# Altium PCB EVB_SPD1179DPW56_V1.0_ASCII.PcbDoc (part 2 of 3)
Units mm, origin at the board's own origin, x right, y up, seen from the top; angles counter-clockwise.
Board outline 135 x 90 mm, 4 copper layers (Top Layer, GND, L3, Bottom Layer), stack 0.603 mm thick; 336 components, 177 nets, 814 pads, 1056 vias.
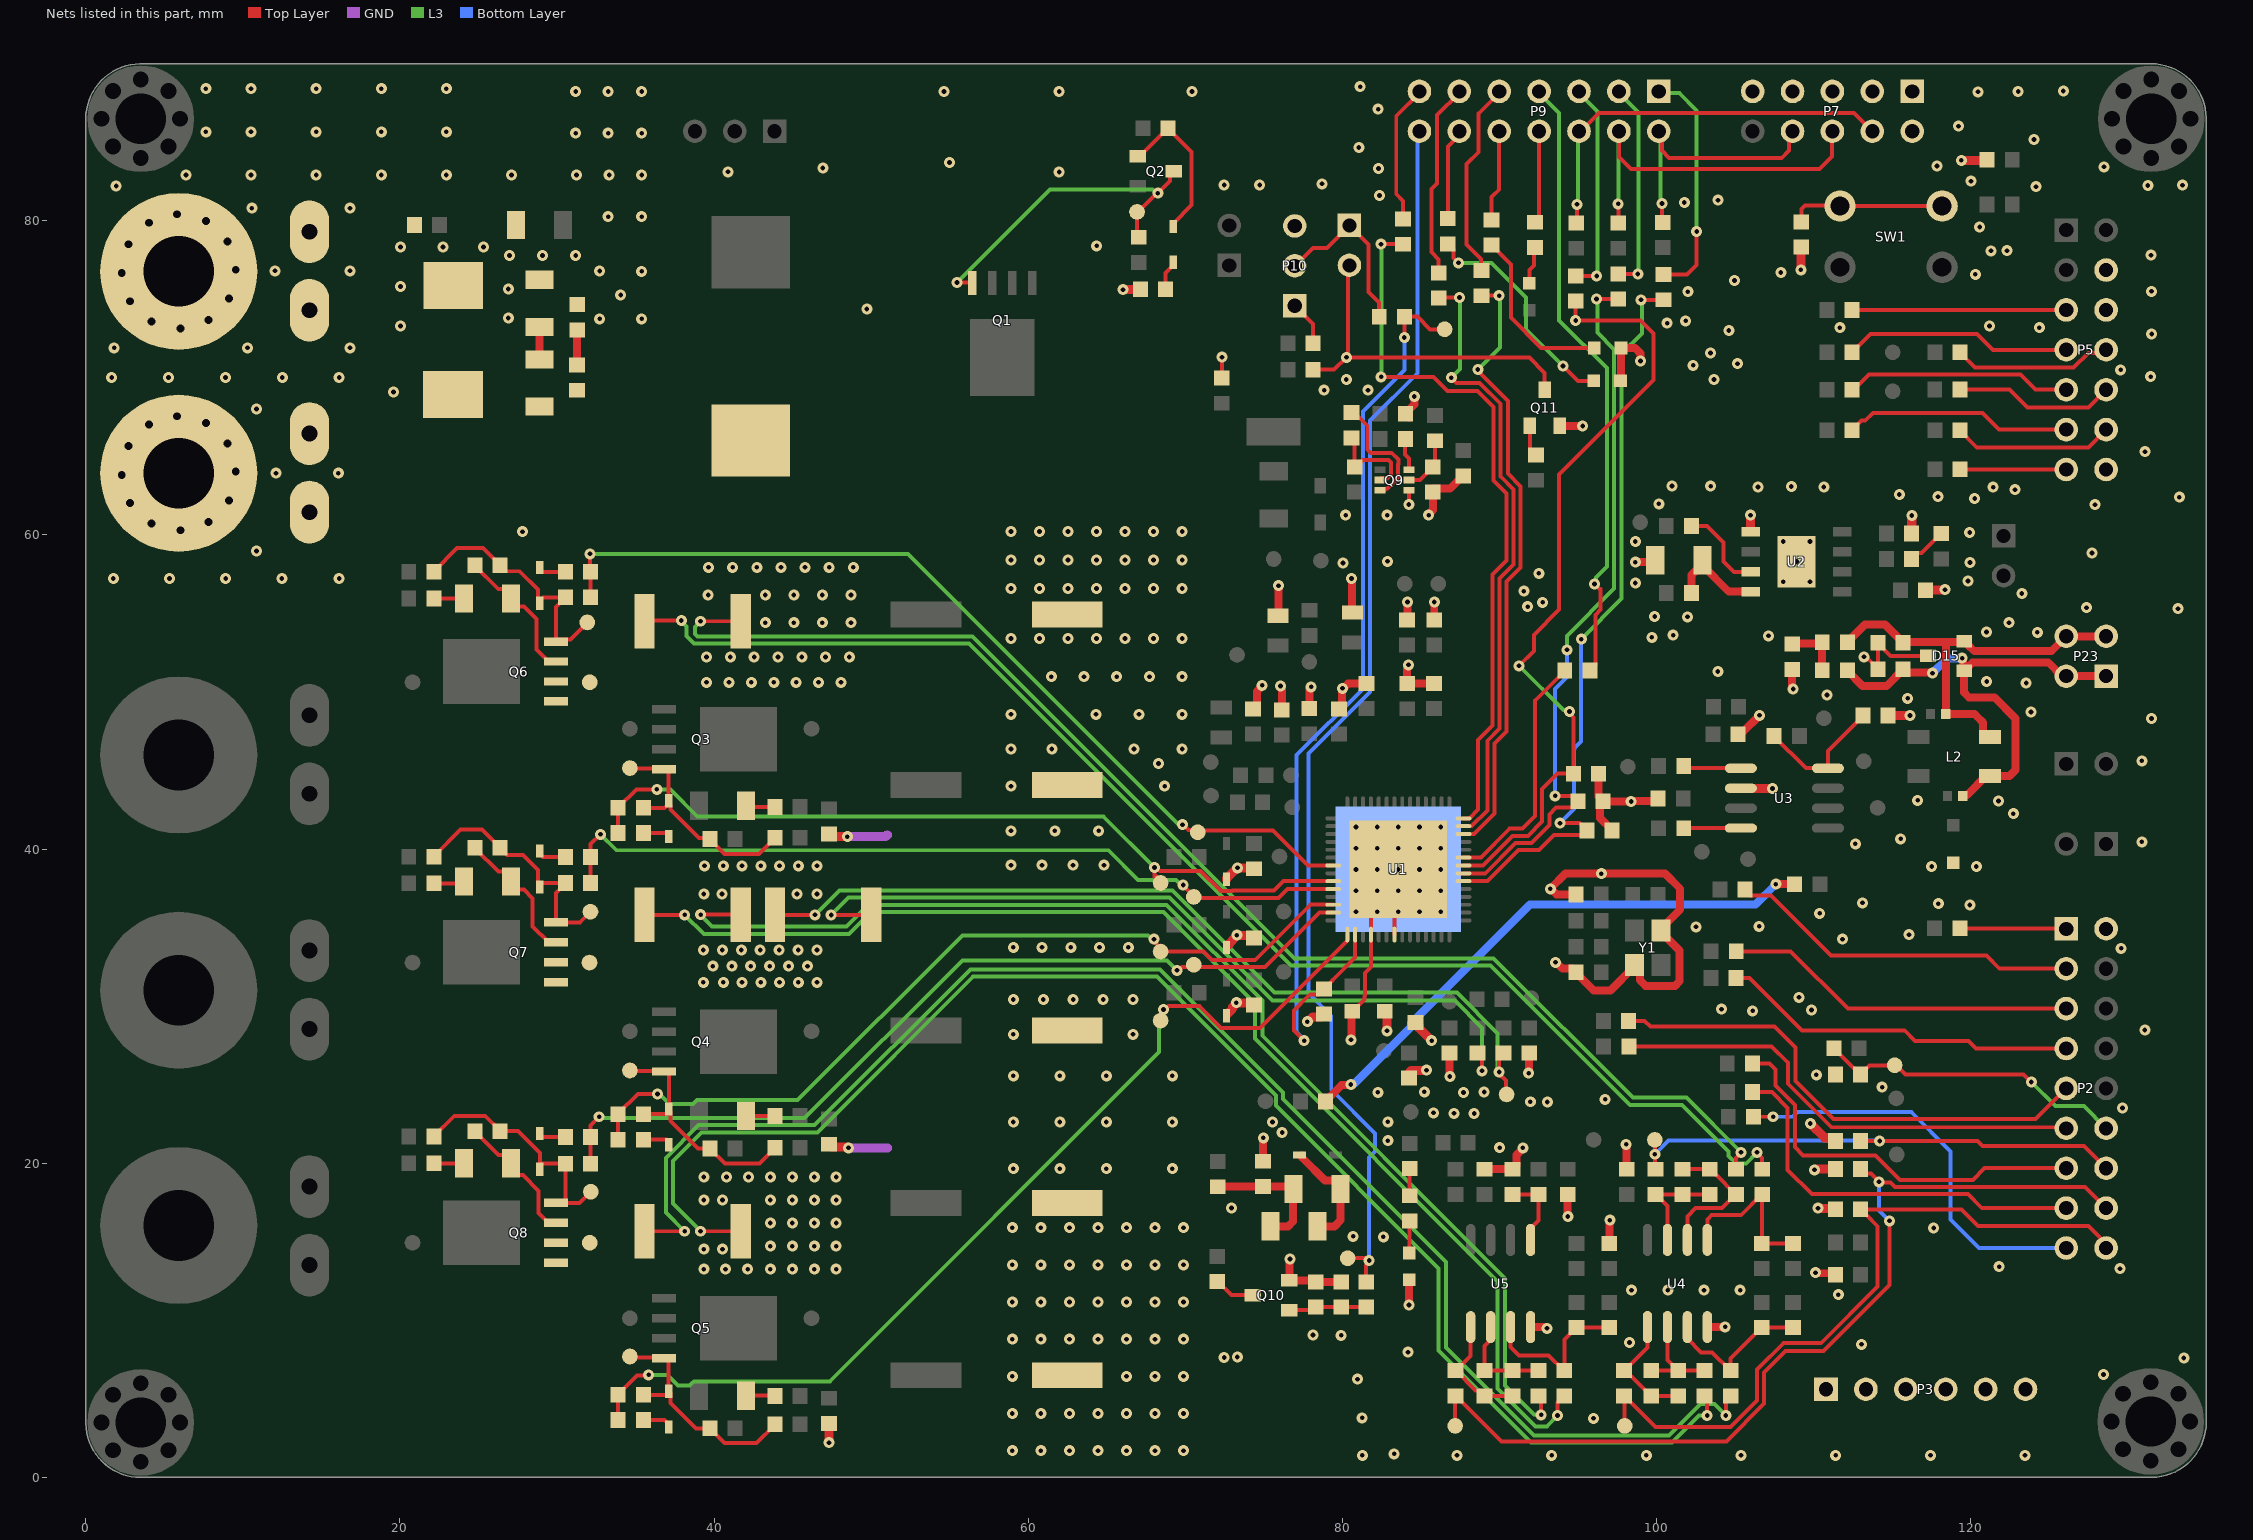
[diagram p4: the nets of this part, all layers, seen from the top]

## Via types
v1: diameter 0.7, hole 0.3, Top Layer to Bottom Layer, tented both sides, 810 vias
v2: diameter 0.5, hole 0.2, Top Layer to Bottom Layer, tented both sides, 161 vias
v3: diameter 0.9, hole 0.5, Top Layer to Bottom Layer, 60 vias
v4: diameter 0.6, hole 0.3, Top Layer to Bottom Layer, tented top, 25 vias

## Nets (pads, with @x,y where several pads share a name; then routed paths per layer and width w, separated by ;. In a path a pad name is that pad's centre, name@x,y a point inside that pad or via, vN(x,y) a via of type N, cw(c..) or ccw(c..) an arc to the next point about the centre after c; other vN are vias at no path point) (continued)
GND: C1.2 C2.1 C5.2 C6.2 C7.1 C8.1 C10.2 C11.1 C12.1 C13.1 C14.2 C15.2 C16.1 C17.1 C18.1 C19.1 C23.1 C24.1 C29.1 C30.1 C31.1 C32.1 C33.1 C34.1 C35.1 C36.1 C37.1 C38.1 C39.1 C40.1 C41.1 C44.1 C52.1 C53.1 C54.1 C55.1 C57.1 C58.1 C61.1 C62.1 C63.1 C64.1 C70.1 C71.1 C72.1 C73.1 C74.1 C77.1 C78.1 C80.1 C81.1 C83.1 C84.1 C85.2 C86.1 C87.2 C90.1 D1.1 D3.2 D4.2 D5.2 D13.2 D14.2 D15.3 D17.2 D18.1 P2.2 P3.1 P3.2 P3.3 P3.4 P3.5 P3.6 P5.4 P5.6 P5.14 P6.1 P7.1 P7.2 P7.3 P7.5 P7.7 P7.9 P10.3 pad.1@5.918,76.784 Q9.1 Q10.2 Q11.2 R7.1 R9.2 R11.1 R55.1 R57.1 R58.1 R85.2 R86.1 R94.1 R98.2 R99.1 R109.2 U1.46 U1.49 U1.57 U2.5 U2.9 U3.2 U4.4 U5.4 Y1.2 Y1.4 | length 203
  Top Layer w0.254: v1(47.459,35.808) 50,35.808 R55.1@50.005,35.814 ; R109.2@72.314,69.99 72.339,70.015 v1(72.339,71.323) ; C78.1@80.629,29.68 80.654,29.68 81.402,30.428 81.402,30.615 81.456,30.67 81.456,31.89 81.439,31.907 81.439,32.117 81.816,32.494 U1.46@81.816,34.187 ; U1.46@81.816,34.56 81.816,36.96 v4(82.216,37.359) U1.57@83.316,38.46 ; C7.1@82.703,29.68 C7.1@82.85,29.533 ; U1.49@83.316,34.56 U1.57@83.316,38.46 ; v4(83.566,38.71) U1.57@83.316,38.46 ; v1(84.232,61.945) Q9.1@84.232,62.85 ; R58.1@88.605,27.021 88.901,26.725 88.898,26.722 v1(88.898,25.889) ; U3.2@105.371,43.877 U3.2@105.382,43.866 ; U2.5@105.98,60.225 U2.5@106.007,60.198 ; v1@107.38,43.866 v1(107.391,43.855) ; R9.2@109.193,78.302 R9.2@109.22,78.329 ; v1(113.208,52.248) 113.293,52.162 113.42,52.162 C62.1@114.097,51.485 ; C62.1@114.097,51.46 C62.1@114.097,51.485 ; C54.1@114.097,53.137 C54.1@114.097,53.112 ; R86.1@114.749,48.514 R86.1@114.841,48.423 ; D15.3@117.29,52.299 114.91,52.299 C54.1@114.097,53.112 ; R11.1@121.004,83.849 R11.1@121.052,83.897 ; C62.1@114.097,51.485 C54.1@114.097,53.112
  Top Layer w0.508: C39.1@74.312,48.934 74.337,48.934 74.558,49.155 74.558,50.046 74.893,50.381 v1(74.893,50.433) ; C77.1@74.955,20.129 74.964,20.138 74.964,21.611 v1(74.973,21.62) ; C38.1@75.908,54.861 75.924,54.877 75.924,56.761 v1(75.94,56.777) ; v1(76.062,50.386) 76.062,50.334 76.144,50.253 C37.1@76.144,48.868 ; v1(76.667,13.9) 76.639,13.872 76.639,12.579 Q10.2@76.611,12.551 78.199,12.551 C80.1@78.313,12.437 R94.1@79.939,12.437 ; C36.1@77.9,48.947 77.9,50.17 78.012,50.283 v1(78.012,50.335) ; C33.1@79.785,48.922 79.977,49.114 79.977,50.204 v1(80.014,50.241) 80.066,50.241 80.375,50.55 C84.1@81.538,50.55 ; v1(80.557,27.861) 80.593,27.897 80.593,29.644 C78.1@80.629,29.68 ; v1@80.582,57.174 v1(80.582,57.226) 80.612,57.197 80.612,55.09 C35.1@80.642,55.06 ; C31.1@84.122,54.584 84.136,54.599 84.136,55.713 v1(84.15,55.728) ; v1@84.195,61.982 v1(84.232,61.945) ; v1(84.209,51.73) 84.209,51.678 84.128,51.597 C32.1@84.128,50.537 84.13,50.54 85.83,50.54 C30.1@85.833,50.542 ; R98.2@84.231,67.47 84.01,67.691 R98.2@84.01,67.716 84.01,67.741 84.585,68.316 v1(84.585,68.815) ; v1(84.244,10.977) 84.252,10.986 84.252,12.577 D17.2@84.261,12.586 ; v1(85.496,61.265) 85.496,61.317 85.765,61.586 R99.1@85.765,62.728 ; R99.1@85.83,62.949 86.857,62.949 87.676,63.768 C83.1@87.701,63.768 ; C29.1@85.852,54.584 v1(85.852,55.728) ; C53.1@86.827,27.021 86.835,27.013 86.835,25.53 v1(86.842,25.523) ; C70.1@89.057,19.621 R85.2@90.84,19.621 90.865,19.621 91.086,19.842 91.086,20.523 91.491,20.928 v1(91.491,20.98) ; v1(91.861,25.734) 91.884,25.757 91.884,26.998 C52.1@91.907,27.021 ; U5.4@91.983,9.572 92.898,9.572 92.983,9.487 v1(93.035,9.487) ; v1(93.565,32.79) 93.617,32.79 94.005,32.402 94.661,32.402 94.882,32.181 C12.1@94.882,32.156 ; Q11.2@93.835,66.947 95.284,66.947 v1(95.298,66.933) ; C72.1@94.345,18.021 94.349,18.017 94.349,16.62 v1(94.353,16.616) ; C12.1@94.882,32.131 96.007,31.006 97.066,31.006 98.591,32.531 Y1.4@98.591,32.631 98.937,32.285 98.937,31.67 99.314,31.293 101.175,31.293 101.473,31.59 101.473,33.549 100.291,34.731 Y1.2@100.291,34.831 100.291,34.931 101.51,36.15 101.51,37.474 100.543,38.441 94.21,38.441 v1(93.241,37.472) 93.282,37.472 93.645,37.109 C13.1@94.882,37.109 ; C87.2@96.321,44.803 96.321,43.354 96.608,43.067 C86.1@96.608,43.042 ; C74.1@96.987,14.897 97.007,14.917 97.007,16.354 v1(97.027,16.374) ; C85.2@97.181,41.18 97.181,41.205 96.406,41.98 96.406,42.84 C86.1@96.608,43.042 ; D13.2@97.711,69.809 97.727,69.825 97.727,71.889 D14.2@97.743,71.905 98.646,71.905 98.987,71.564 v1(98.987,71.077) ; v1(98.075,21.208) 98.09,21.192 98.09,19.637 C71.1@98.106,19.621 ; v1(98.654,58.268) 99.795,58.268 C55.1@99.922,58.395 ; C58.1@100.104,43.197 99.98,43.073 98.423,43.073 v1(98.386,43.036) 98.383,43.039 96.611,43.039 C86.1@96.608,43.042 ; U4.4@103.237,9.572 103.244,9.579 104.365,9.579 v1(104.372,9.586) ; C61.1@105.015,47.141 C61.1@105.194,47.32 C61.1@105.194,47.345 ; C61.1@105.531,47.492 106.521,48.483 v1(106.558,48.52) ; C57.1@108.636,51.448 108.636,50.315 108.704,50.247 v1(108.704,50.195) ; v1(110.126,13.035) 110.163,12.998 111.297,12.998 C73.1@111.392,12.903
  Top Layer w0.58: v1(47.32,2.21) C18.1@47.32,3.442 ; C16.1@47.32,21.212 47.505,21.027 48.485,21.027 48.532,20.98 v1(48.565,20.98) ; C17.1@47.32,40.964 47.469,40.815 48.466,40.815 v1(48.489,40.792) ; v1(66.04,75.616) 66.053,75.629 67.132,75.629 R7.1@67.145,75.641 ; D5.2@72.628,38.078 72.628,38.148 73.269,38.788 73.307,38.788 v1(73.33,38.811) 73.353,38.788 74.343,38.788 C24.1@74.381,38.751 ; D3.2@72.688,29.521 73.011,29.843 73.011,29.951 73.254,30.194 v1(73.254,30.226) 73.277,30.203 74.242,30.203 C19.1@74.381,30.064 ; D4.2@72.688,33.864 73.011,34.187 73.011,34.218 73.279,34.486 v1(73.279,34.519) 73.302,34.496 74.239,34.496 C23.1@74.381,34.354 ; v1(77.773,29.011) 77.805,29.011 78.116,29.321 78.644,29.321 C8.1@78.829,29.506 ; v1(82.85,28.429) C7.1@82.85,29.533 ; C40.1@84.271,25.785 84.388,25.901 85.331,25.901 v1(85.354,25.924) ; C41.1@84.653,28.953 84.678,28.953 84.863,28.768 84.863,28.625 v1(85.686,27.802) ; C58.1@100.104,43.197 C58.1@100.104,43.222 ; U3.2@105.382,43.866 v1@107.38,43.866 ; U2.5@105.98,60.225 v1(105.98,61.257) ; v1(109.193,76.879) R9.2@109.193,78.302 ; v1(109.796,22.534) 110.708,21.622 111.207,21.622 111.392,21.437 C63.1@111.392,21.412 ; v1(110.058,19.583) 110.091,19.583 110.141,19.634 C81.1@111.392,19.634 ; v1(110.287,17.145) 110.31,17.122 111.339,17.122 C64.1@111.392,17.069 ; R86.1@114.749,48.514 v1(116.138,48.514) ; R57.1@116.243,60.096 116.249,60.103 116.249,61.233 v1(116.256,61.239) ; C44.1@117.132,56.49 117.145,56.502 118.351,56.502 v1(118.364,56.515) ; v1(119.41,83.849) R11.1@121.004,83.849
  GND w0.58: v1(48.489,40.792) 50.927,40.792 51.029,40.894 ; v1(48.565,20.98) 51.054,20.98
  L3 w0.254: v1(47.459,35.808) 48.557,36.906 69.003,36.906 75.556,30.353 87.161,30.353 88.898,28.616 v1(88.898,25.889)
  other v1: 81.272,1.401 87.3,1.401 93.328,1.401 99.357,1.401 105.385,1.401 111.413,1.401 117.441,1.401 123.469,1.401 83.297,1.505 58.991,1.702 60.808,1.702 62.624,1.702 64.44,1.702 66.256,1.702 68.072,1.702 69.888,1.702 95.987,3.759 81.259,3.79 58.991,4.068 60.808,4.068 62.624,4.068 64.44,4.068 66.256,4.068 68.072,4.068 69.888,4.068 80.966,6.256 58.991,6.435 66.256,6.435 68.072,6.435 69.888,6.435 128.465,6.558 133.571,7.599 72.48,7.631 73.317,7.663 84.177,7.97 113.053,8.476 98.289,8.592 58.991,8.801 60.808,8.801 62.624,8.801 64.44,8.801 66.256,8.801 68.072,8.801 69.888,8.801 79.931,9.044 78.134,9.066 58.991,11.168 60.808,11.168 62.624,11.168 64.44,11.168 66.256,11.168 68.072,11.168 69.888,11.168 111.574,11.638 98.416,11.919 100.719,11.919 103.022,11.919 105.325,11.919 129.507,13.289 121.819,13.415 58.991,13.534 60.808,13.534 62.624,13.534 64.44,13.534 66.256,13.534 68.072,13.534 69.888,13.534 82.61,15.316 80.694,15.351 117.645,15.879 58.991,15.9 60.808,15.9 62.624,15.9 64.44,15.9 66.256,15.9 68.072,15.9 69.888,15.9 72.94,17.151 59.055,19.66 62.014,19.66 64.973,19.66 69.173,19.66 90.013,20.989 82.897,21.435 76.173,21.965 59.055,22.624 62.014,22.631 64.973,22.624 69.173,22.624 75.554,22.621 82.898,22.636 88.392,23.162 87.106,23.181 85.81,23.21 129.667,23.52 93.048,23.899 91.968,23.917 96.73,24.068 82.262,24.513 87.709,24.501 85.217,24.549 89.028,24.534 114.368,24.846 59.055,25.571 62.014,25.571 64.973,25.571 69.173,25.571 110.177,25.633 59.055,28.212 66.675,28.212 131.09,28.481 106.128,29.705 109.873,29.764 104.139,29.81 59.055,30.429 60.96,30.429 62.865,30.429 64.77,30.429 66.675,30.429 109.075,30.561 129.583,33.685 59.055,33.749 60.884,33.749 62.713,33.749 64.541,33.749 66.37,33.749 111.848,34.268 116.078,34.556 102.519,35.052 106.542,35.086 110.391,35.915 119.946,36.445 117.946,36.53 113.124,36.58 96.484,38.438 117.518,38.892 120.363,38.892 58.903,38.982 60.878,38.982 62.854,38.982 64.83,38.982 112.664,40.334 130.902,40.462 115.547,40.655 58.903,41.166 61.697,41.166 64.491,41.166 122.719,42.258 121.772,43.059 116.633,43.112 58.903,44.011 68.691,44.011 68.3,45.452 130.902,45.618 58.903,46.373 61.503,46.373 66.735,46.373 69.799,46.373 131.512,48.315 58.903,48.583 64.313,48.583 67.056,48.583 69.799,48.583 123.842,48.732 115.997,49.603 110.861,49.814 123.541,50.577 121.023,50.677 61.468,50.978 63.551,50.978 65.634,50.978 67.716,50.978 69.799,50.978 103.91,51.313 58.903,53.416 60.719,53.416 62.535,53.416 64.351,53.416 66.167,53.416 67.983,53.416 69.799,53.416 99.7,53.483 107.133,53.582 101.064,53.619 124.249,53.802 121.006,53.823 122.447,54.416 101.973,54.792 99.883,54.805 133.209,55.306 127.373,55.376 91.796,55.439 92.754,55.712 123.257,56.28 91.556,56.423 58.903,56.591 60.719,56.591 62.535,56.591 64.351,56.591 66.167,56.591 67.983,56.591 69.799,56.591 98.654,56.947 108.066,57.026 109.768,57.026 119.833,57.077 92.506,57.56 80.041,58.22 119.956,58.243 82.872,58.323 108.917,58.309 58.903,58.407 60.719,58.407 62.535,58.407 64.351,58.407 66.167,58.407 67.983,58.407 69.799,58.407 127.726,58.847 98.654,59.588 108.066,59.592 109.768,59.592 119.943,60.163 58.903,60.223 60.719,60.223 62.535,60.223 64.351,60.223 66.167,60.223 67.983,60.223 69.799,60.223 80.213,61.265 82.855,61.265 127.923,61.933 100.146,61.982 120.258,62.33 133.284,62.408 117.918,62.436 115.457,62.585 122.825,62.884 121.438,63.043 106.467,63.061 110.658,63.061 108.584,63.089 100.989,63.12 103.447,63.107 131.107,65.302 78.842,69.219 81.628,69.219 80.251,69.895 103.659,69.906 131.466,70.078 129.557,70.515 102.334,70.804 105.164,70.91 103.436,71.591 1.809,71.914 10.293,71.914 16.821,71.914 131.524,72.795 104.607,73.013 111.671,73.197 124.37,73.197 20.041,73.304 121.201,73.309 100.683,73.488 101.863,73.631 32.715,73.762 35.393,73.762 26.899,73.812 49.725,74.392 34.054,75.286 101.998,75.495 131.515,75.51 26.899,75.667 20.041,75.819 104.972,76.209 120.298,76.595 107.914,76.707 35.393,76.784 12.045,76.816 16.821,76.816 32.715,76.81 26.975,77.8 29.083,77.8 31.191,77.8 131.481,77.818 121.293,78.096 122.314,78.103 20.041,78.334 22.746,78.334 25.324,78.334 64.364,78.413 120.579,79.612 33.259,80.262 35.393,80.262 10.572,80.804 16.821,80.804 101.773,81.17 103.911,81.314 82.368,81.614 124.165,82.178 1.93,82.22 131.281,82.25 74.742,82.278 133.494,82.275 72.48,82.288 78.703,82.356 120.028,82.527 6.378,82.92 10.523,82.92 14.668,82.92 18.813,82.92 22.958,82.92 27.103,82.92 31.248,82.92 33.32,82.92 35.393,82.92 40.891,83.121 61.976,83.112 82.307,83.332 46.928,83.367 128.491,83.443 117.866,83.487 54.989,83.715 81.053,84.673 124.03,85.186 31.191,85.579 33.259,85.579 35.393,85.579 7.645,85.669 10.523,85.669 14.668,85.669 18.813,85.669 22.958,85.669 119.231,86.025 82.282,87.106 120.473,88.212 31.191,88.237 33.259,88.237 35.393,88.24 54.635,88.24 61.976,88.24 70.434,88.24 123.028,88.23 125.898,88.265 7.645,88.417 10.523,88.417 14.668,88.417 18.813,88.417 22.958,88.417 81.138,88.543
  other v3: 6.02,73.152 4.19,73.588 7.822,73.689 2.823,74.88 9.115,75.056 2.286,76.683 9.55,76.886 2.722,78.512 9.013,78.688 4.014,79.879 7.646,79.981 5.817,80.416
  other v4: 80.865,36.009 82.216,36.009 83.566,36.009 84.916,36.009 86.267,36.009 80.865,37.359 83.566,37.359 84.916,37.359 86.267,37.359 80.865,38.71 82.216,38.71 84.916,38.71 86.267,38.71 80.865,40.06 82.216,40.06 83.566,40.06 84.916,40.06 86.267,40.06 80.865,41.411 82.216,41.411 83.566,41.411 84.916,41.411 86.267,41.411
HALL_A: P7.8 P9.2 R117.1 | length 16.7
  Top Layer w0.254: P9.2@100.339,85.414 100.339,84.466 100.81,83.995 107.975,83.995 108.444,84.465 P7.8@108.444,85.414 ; v1(100.355,81.106) 100.355,79.942 R117.1@100.397,79.899
  Top Layer w0.508: P9.2@100.149,85.604 P9.2@100.339,85.414 ; P7.8@108.444,85.414 P7.8@108.634,85.604
  L3 w0.254: P9.2@100.149,85.604 100.27,85.484 100.27,81.191 v1(100.355,81.106)
HALL_B: P7.6 P9.4 R118.1 | length 23
  Top Layer w0.254: R118.1@97.57,79.858 v1@97.57,80.881 ; P9.4@97.609,85.604 97.609,84.078 98.388,83.299 110.386,83.299 111.174,84.087 111.174,85.675 P7.6@111.202,85.704
  Top Layer w0.508: P9.4@97.59,85.585 P9.4@97.609,85.604
  L3 w0.254: v1@97.583,81.111 P9.4@97.583,85.578
  L3 w0.508: v1(97.558,81.085) v1@97.583,81.111 ; P9.4@97.583,85.578 P9.4@97.609,85.604
HALL_C: P7.4 P9.6 R119.1 | length 25.6
  Top Layer w0.254: v1(94.94,81.055) 94.94,79.943 R119.1@94.958,79.925 ; P9.6@95.069,85.604 96.327,86.862 112.584,86.862 P7.4@113.742,85.704
  Top Layer w0.508: R119.1@94.889,79.856 R119.1@94.958,79.925 ; P9.6@94.979,85.514 P9.6@95.069,85.604
  L3 w0.254: v1(94.94,81.055) 95.005,81.12 95.005,85.54 P9.6@95.069,85.604
HO_U: R24.2 R27.2 TP11.1 U1.43 | length 63.7
  Top Layer w0.254: R24.2@33.896,3.658 R27.2@33.896,5.258 33.896,5.283 35.108,6.495 35.806,6.495 v1(35.839,6.528) ; TP11.1@68.428,29.083 TP11.1@68.428,29.285 ; v1(68.616,29.79) 68.737,29.79 68.944,29.997 70.901,29.997 72.272,28.626 74.753,28.626 80.316,34.189 U1.43@80.316,34.56
  L3 w0.254: v1(35.839,6.528) 37.022,6.528 37.712,5.837 38.425,5.837 38.71,6.121 47.371,6.121 68.342,27.093 68.342,29.418 68.616,29.692 v1(68.616,29.79)
HO_V: R23.2 R26.2 TP21.1 U1.40 | length 54.7
  Top Layer w0.254: R23.2@33.896,21.504 33.896,23.155 35.151,24.409 v1(36.398,24.409) ; v1(68.005,34.266) 68.091,34.18 68.091,34.016 68.428,33.679 TP21.1@68.428,33.477 71.172,33.477 71.697,32.952 74.456,32.952 77.963,36.46 U1.40@79.416,36.46
  L3 w0.254: v1(36.398,24.409) 36.519,24.409 37.154,23.774 38.659,23.774 38.913,24.028 45.325,24.028 55.807,34.51 67.64,34.51 67.885,34.266 v1(68.005,34.266)
HO_W: R22.2 R25.2 TP36.1 U1.37 | length 52.2
  Top Layer w0.254: R22.2@33.896,41.028 33.896,42.653 35.049,43.805 v1(36.357,43.805) ; TP36.1@68.428,37.846 TP36.1@68.285,37.989 ; U1.37@79.416,37.96 76.245,37.96 75.638,37.353 73.016,37.353 72.993,37.331 72.254,37.331 72.232,37.353 70.977,38.608 68.396,38.608 68.167,38.837 v1(68.047,38.837) 68.047,38.398 ; 68.047,38.398 68.047,38.227 TP36.1@68.285,37.989 ; 68.047,38.398 68.285,38.159 TP36.1@68.285,37.989
  L3 w0.254: v1(36.357,43.805) 36.378,43.785 37.215,43.785 38.937,42.062 64.805,42.062 68.03,38.837 v1(68.047,38.837)
IBS+: R51.1 R52.1 R53.1 R54.1 R55.2 R70.2 R71.2 R89.2 TP28.1 | length 314
  Top Layer w0.254: v1(39.141,15.672) R53.1@41.7,15.672 ; v1(39.141,54.508) R51.1@41.7,54.508 ; v1(39.15,35.823) 41.691,35.823 R52.1@41.7,35.814 ; R55.2@43.873,35.814 v1(46.431,35.814) ; R54.1@90.256,27.021 89.984,26.749 v1(89.984,25.808) 89.984,25.688 90.408,25.264 90.408,24.429 TP28.1@90.454,24.383 TP28.1@90.391,24.383 ; R89.2@92.491,5.194 92.659,5.026 v1(92.659,3.982) ; R71.2@103.057,5.194 103.226,5.026 v1(103.226,3.937) ; R70.2@105.057,19.621 105.057,20.346 105.385,20.674 v1(105.385,20.701)
  L3 w0.254: v1(39.141,15.672) 39.141,15.69 37.389,17.442 37.389,20.156 39.204,21.971 46.595,21.971 56.501,31.877 68.195,31.877 75.77,24.302 75.77,23.667 86.131,13.306 86.131,8.091 92.009,2.213 100.994,2.213 102.709,3.928 103.217,3.928 v1(103.226,3.937) ; v1(39.141,54.508) 39.141,54.492 38.786,54.137 38.786,53.692 38.935,53.543 56.464,53.543 76.962,33.045 89.637,33.045 98.501,24.181 101.905,24.181 v1(105.385,20.701) ; v1(39.15,35.823) 39.15,35.805 39.878,35.077 48.426,35.077 49.798,36.449 68.813,36.449 74.903,30.359 74.903,28.119 90.348,12.675 90.348,5.842 92.193,3.997 92.645,3.997 v1(92.659,3.982) ; v1(46.431,35.814) 47.981,37.363 69.192,37.363 75.694,30.861 87.3,30.861 89.891,28.27 v1@89.891,25.89
  other v1: 39.345,13.259 40.729,13.259 42.139,13.259 43.586,13.259 44.983,13.259 46.38,13.259 47.777,13.259 39.345,14.529 40.538,14.529 43.586,14.726 44.983,14.726 46.38,14.726 47.777,14.726 43.586,16.192 44.983,16.192 46.38,16.192 47.777,16.192 39.345,17.659 40.538,17.659 43.586,17.659 44.983,17.659 46.38,17.659 47.777,17.659 39.345,19.126 40.792,19.126 42.189,19.126 43.586,19.126 44.983,19.126 46.38,19.126 47.777,19.126 39.319,31.521 40.589,31.521 41.783,31.521 42.977,31.521 44.171,31.521 45.364,31.521 46.558,31.521 39.922,32.55 41.129,32.55 42.335,32.55 43.542,32.55 44.748,32.55 45.955,32.55 39.319,33.579 40.526,33.579 41.732,33.579 42.939,33.579 44.145,33.579 45.352,33.579 46.558,33.579 39.345,37.141 40.509,37.141 45.284,37.141 46.558,37.141 39.395,38.938 40.589,38.938 41.783,38.938 42.977,38.938 44.171,38.938 45.364,38.938 46.558,38.938 39.522,50.622 40.949,50.622 42.376,50.622 43.802,50.622 45.229,50.622 46.656,50.622 48.082,50.622 39.522,52.229 41.038,52.229 42.553,52.229 44.069,52.229 45.585,52.229 47.1,52.229 48.616,52.229 43.26,54.413 45.077,54.413 46.895,54.413 48.713,54.413 39.624,56.185 43.26,56.185 45.077,56.185 46.895,56.185 48.713,56.185 39.645,57.944 41.182,57.944 42.718,57.944 44.255,57.944 45.792,57.944 47.328,57.944 48.865,57.944
IDC: C90.2 P2.12 R122.1 TP47.1 | length 19.8
  Top Layer w0.254: R122.1@111.29,27.33 111.29,27.305 112.569,26.027 112.644,26.027 C90.2@112.992,25.679 ; C90.2@112.992,25.654 C90.2@112.992,25.679 ; TP47.1@115.164,26.238 113.576,26.238 113.365,26.027 113.34,26.027 C90.2@112.992,25.679 ; TP47.1@115.292,26.213 115.851,25.654 123.378,25.654 v1(123.861,25.171)
  L3 w0.254: v1(123.861,25.171) 125.398,23.634 127.217,23.634 P2.12@128.626,22.225
IO6: C85.1 R64.2 U1.6 | length 48.1
  Top Layer w0.254: U1.6@87.716,37.96 89.241,37.96 91.216,39.935 92.51,39.935 93.484,40.909 95.309,40.909 C85.1@95.581,41.18 95.581,41.205 95.233,41.553 95.208,41.553 95.111,41.65 v1(93.858,41.65) ; v1(99.016,74.975) R64.2@100.448,74.975
  L3 w0.254: v1(95.212,53.37) 95.212,53.381 97.777,55.946 97.777,71.547 99.065,72.835 99.065,74.925 v1(99.016,74.975)
  Bottom Layer w0.254: v1(93.858,41.65) 94.751,42.543 94.751,46.355 94.771,46.375 94.771,46.428 95.206,46.863 95.206,53.364 v1(95.212,53.37)
IO7: C86.2 R125.2 U1.7 | length 46.3
  Top Layer w0.254: U1.7@87.716,38.46 89.099,38.46 91.028,40.389 92.041,40.389 93.178,41.525 93.178,42.212 93.609,42.643 94.609,42.643 94.635,42.669 94.66,42.669 95.008,43.017 C86.2@95.008,43.042 95.008,43.048 94.66,43.396 v1(93.554,43.396) ; v1(96.184,75.019) R125.2@97.563,75.019
  L3 w0.254: v1(94.3,52.689) 94.3,53.578 97.309,56.587 97.309,71.803 96.233,72.879 96.233,74.969 v1(96.184,75.019)
  Bottom Layer w0.254: v1(93.554,43.396) 93.527,43.423 93.527,50.181 94.3,50.954 v1(94.3,52.689)
IO8: C87.1 R126.2 U1.8 | length 50.3
  Top Layer w0.254: U1.8@87.716,38.96 88.957,38.96 90.843,40.846 91.809,40.846 92.72,41.757 92.72,43.817 93.707,44.803 C87.1@94.721,44.803 94.721,48.39 94.466,48.645 v1(94.466,48.766) ; v1(91.254,51.675) 92.188,52.608 92.188,53.641 93.794,55.246 93.794,63.859 99.808,69.874 99.808,72.832 98.98,73.66 v1(94.856,73.66) R126.2@94.856,74.894
  L3 w0.254: v1(91.254,51.675) 94.078,48.851 94.38,48.851 v1(94.466,48.766)
IO9: R103.2 U1.9 | length 15.7
  Top Layer w0.254: U1.9@87.716,39.46 88.815,39.46 90.658,41.303 91.469,41.303 92.263,42.097 92.263,49.447 94.16,51.344 R103.2@94.16,51.369
IO12: R3.2 U1.12 | length 39
  Top Layer w0.254: U1.12@87.716,40.96 87.718,40.962 88.382,40.962 89.696,42.275 89.696,46.711 90.463,47.478 90.463,57.038 91.357,57.932 91.357,63.09 90.542,63.904 90.542,68.517 88.623,70.436 v1(88.623,70.53) ; R3.2@88.857,75.233 v1(89.986,75.233)
  L3 w0.254: v1(88.623,70.53) 90.036,71.943 90.036,75.184 v1(89.986,75.233)
IO13: R2.2 U1.13 | length 39.4
  Top Layer w0.254: R2.2@86.15,75.071 R2.2@86.133,75.088 86.168,75.123 v1(87.459,75.123) ; v1(86.94,70.017) 87.282,69.676 88.736,69.676 90.085,68.328 90.085,63.715 90.9,62.9 90.9,58.121 90.006,57.227 90.006,47.668 89.238,46.9 89.238,42.464 88.236,41.462 87.718,41.462 U1.13@87.716,41.46
  L3 w0.254: v1(86.94,70.017) 87.503,70.58 87.503,75.079 v1(87.459,75.123)
IO14: R6.2 U1.14 | length 45.7
  Top Layer w0.254: v1(82.466,78.512) R6.2@83.861,78.512 ; v1(82.472,70.073) 85.797,70.073 86.694,69.175 88.591,69.175 89.628,68.138 89.628,63.466 90.443,62.651 90.443,58.375 89.548,57.481 89.548,47.857 88.639,46.948 88.639,42.512 88.087,41.96 U1.14@87.716,41.96
  L3 w0.254: v1(82.466,78.512) 82.494,78.484 82.494,70.095 v1(82.472,70.073)
IU: C64.2 P2.18 R73.1 TP34.1 | length 45.9
  Top Layer w0.254: R73.1@97.935,5.194 97.974,5.155 TP34.1@97.974,3.277 ; R73.1@97.96,5.194 99.948,3.206 104.722,3.206 106.401,4.884 106.401,6.858 108.102,8.56 110.49,8.56 114.071,12.141 114.071,15.989 113.365,16.696 113.34,16.696 112.992,17.044 C64.2@112.992,17.069 119.42,17.069 120.474,16.014 127.495,16.014 128.626,14.883 P2.18@128.626,14.605
IUS+: C48.1 Q8.1 Q8.2 Q8.3 R47.2 R53.2 R75.2 TP26.1 | length 107.1
  Top Layer w0.254: C48.1@24.778,22.047 24.778,22.022 26.271,20.529 26.63,20.529 27.302,19.857 27.302,19.462 27.526,19.238 27.824,19.238 28.829,18.234 28.829,16.821 29.445,16.205 Q8.3@29.94,16.205 ; R53.2@35.567,15.672 v1(38.125,15.672) ; v1(104.419,3.937) 104.419,4.889 R75.2@104.725,5.194
  L3 w0.254: v1(38.125,15.672) 36.932,16.866 36.932,20.345 39.014,22.428 46.406,22.428 56.312,32.334 68.384,32.334 76.227,24.491 76.227,24.081 86.589,13.72 86.589,8.28 92.198,2.671 100.805,2.671 102.802,4.668 103.688,4.668 v1(104.419,3.937)
IV: C81.2 P2.16 R90.1 TP37.1 | length 59.6
  Top Layer w0.254: TP37.1@87.182,3.277 87.182,5.169 R90.1@87.208,5.194 87.233,5.194 90.137,2.29 104.453,2.29 106.858,4.695 106.858,6.669 108.227,8.038 110.633,8.038 114.833,12.239 v1(114.833,16.338) ; C81.2@112.992,19.634 113.288,19.338 113.656,19.338 114.22,18.774 114.904,18.774 115.192,18.486 127.285,18.486 P2.16@128.626,17.145
  Bottom Layer w0.254: v1(114.173,18.821) 114.173,16.998 v1(114.833,16.338)
IVS+: C47.1 Q7.1 Q7.2 Q7.3 R46.2 R52.2 R92.2 TP25.1 | length 88.7
  Top Layer w0.254: C47.1@24.778,40.08 24.778,40.055 26.271,38.562 26.63,38.562 27.078,38.114 R46.2@27.078,37.946 27.078,37.866 27.526,37.418 27.885,37.418 28.453,36.85 28.453,35.066 29.445,34.074 Q7.3@29.94,34.074 ; R52.2@35.567,35.814 v1(38.125,35.814) ; v1(93.701,3.937) 93.701,4.762 93.76,4.821 93.76,4.846 94.108,5.194 R92.2@94.133,5.194
  L3 w0.254: v1(38.125,35.814) 39.345,34.595 48.59,34.595 49.987,35.992 68.624,35.992 74.446,30.169 74.446,27.93 89.891,12.485 89.891,5.653 92.292,3.251 93.015,3.251 v1(93.701,3.937)
IW: C63.2 P2.14 R72.1 TP33.1 | length 32.9
  Top Layer w0.254: TP33.1@99.898,21.488 v1(99.898,20.574) 99.898,19.658 R72.1@99.935,19.621 ; C63.2@112.992,21.412 v1(114.208,21.412) 120.445,21.412 120.763,21.094 127.217,21.094 P2.14@128.626,19.685
  Bottom Layer w0.254: v1(99.898,20.574) 100.762,21.438 114.183,21.438 v1(114.208,21.412)
IWS+: C46.1 Q6.1 Q6.2 Q6.3 R45.2 R51.2 R74.2 TP27.1 | length 96.4
  Top Layer w0.254: C46.1@24.778,58.064 24.778,58.039 26.271,56.547 26.63,56.547 27.302,55.875 27.302,55.676 27.526,55.452 27.885,55.452 28.69,54.647 28.69,52.698 29.445,51.943 Q6.3@29.94,51.943 ; R51.2@35.357,54.559 v1(37.915,54.559) ; v1(106.401,20.701) 106.401,20.671 106.725,20.346 R74.2@106.725,19.621
  L3 w0.254: v1(37.915,54.559) 37.915,54.525 38.252,54.187 38.252,53.569 38.735,53.086 56.242,53.086 76.74,32.588 89.447,32.588 98.312,23.724 101.625,23.724 104.597,20.752 104.597,20.455 105.082,19.97 105.687,19.97 106.401,20.683 v1(106.401,20.701)
KL30: C3.2 C4.2 D1.2 L1.1 P1.1 pad.1@5.918,63.932
  other v1: 1.753,57.226 5.328,57.226 8.903,57.226 12.478,57.226 16.129,57.226 10.871,58.979 27.802,60.211 12.116,63.932 16.078,63.932 10.871,68.021 19.597,69.101 1.651,70.028 5.271,70.028 8.89,70.028 12.509,70.028 16.129,70.028
  other v3: 6.02,60.3 4.19,60.735 7.822,60.837 2.823,62.028 9.115,62.204 2.286,63.83 9.55,64.033 2.722,65.66 9.013,65.836 4.014,67.027 7.646,67.128 5.817,67.564
LO_U: R36.2 R42.2 TP19.1 U1.41 | length 56
  Top Layer w0.254: R42.2@32.144,19.972 32.144,22.415 v1(32.69,22.962) ; v1(69.469,32.283) 69.59,32.283 69.803,32.496 70.402,32.496 TP19.1@70.545,32.639 70.686,32.498 75.078,32.498 78.539,35.96 U1.41@79.416,35.96
  L3 w0.254: v1(32.69,22.962) 32.766,22.885 45.771,22.885 55.804,32.918 68.834,32.918 v1(69.469,32.283)
LO_V: R35.2 R41.2 TP23.1 U1.38 | length 52
  Top Layer w0.254: R41.2@32.144,37.845 32.144,40.322 v1(32.766,40.945) ; v1(69.869,37.72) 69.869,37.677 70.545,37.001 TP23.1@70.545,36.957 70.607,36.896 72.056,36.896 72.075,36.877 73.181,36.877 73.2,36.896 75.95,36.896 76.514,37.46 U1.38@79.416,37.46
  L3 w0.254: v1(32.766,40.945) 33.782,39.929 65.126,39.929 67.005,38.049 69.419,38.049 69.748,37.72 v1(69.869,37.72)
LO_W: R34.2 R40.2 TP45.1 U1.35 | length 58.3
  Top Layer w0.254: v1(32.106,58.801) 32.106,57.696 R34.2@32.144,57.658 R40.2@32.144,56.032 ; v1(69.83,41.56) 69.864,41.56 70.21,41.215 70.606,41.215 70.621,41.199 75.586,41.199 77.825,38.96 U1.35@79.416,38.96
  L3 w0.254: v1(32.106,58.801) 52.349,58.801 69.505,41.645 69.745,41.645 v1(69.83,41.56)
MCU_FG: P9.14 R91.2 TP38.1 | length 79.5
  Top Layer w0.254: TP38.1@80.336,13.957 81.434,13.957 81.587,13.805 v1(81.707,13.805) 81.707,13.684 81.513,13.49 R91.2@81.513,12.437
  Bottom Layer w0.254: v1(81.707,13.805) 81.707,20.366 82.085,20.744 82.085,21.91 79.294,24.701 79.294,29.392 77.838,30.848 77.838,46.081 81.771,50.013 81.771,67.291 84.778,70.298 84.778,85.473 P9.14@84.909,85.604
MON: C8.2 R115.1 TP3.1 U1.44 | length 60.8
  Top Layer w0.254: v1(77.567,27.803) 76.909,28.461 76.909,29.723 77.862,30.677 77.89,30.677 77.972,30.758 78.481,30.758 C8.2@78.829,31.106 ; C8.2@79.003,31.28 79.028,31.28 79.376,31.628 79.376,31.653 80.816,33.093 U1.44@80.816,34.56 ; v1(83.949,72.569) R115.1@83.949,73.903 84.78,73.903 85.589,73.094 TP3.1@86.511,73.094
  Bottom Layer w0.254: v1(77.567,27.803) 77.567,27.866 77.081,28.351 77.081,34.103 77.095,34.117 77.095,45.985 81.313,50.203 81.313,67.872 83.949,70.507 v1(83.949,72.569)
NetC2_2: C2.2 C3.1 | length 2.1
  Top Layer w0.508: C3.1@28.88,71.172 C2.2@28.88,73.252
NetC4_1: C4.1 C34.2 | length 2.3
  Top Layer w0.508: C4.1@31.267,70.815 31.28,70.828 31.28,73.05 C34.2@31.293,73.063
NetC9_1: C9.1 D2.1 Q2.1 | length 10
  Top Layer w0.254: Q2.1@66.973,84.11 67.098,84.11 68.518,85.53 68.549,85.53 C9.1@68.897,85.878 ; C9.1@68.897,85.903 C9.1@68.897,85.878 ; D2.1@69.24,79.648 69.24,79.838 70.398,80.996 70.398,84.378 C9.1@68.897,85.878
NetC20_1: C20.1 R32.1 | length 1.9
  Top Layer w0.254: R32.1@42.038,42.755 42.115,42.679 C20.1@43.879,42.679
NetC21_1: C21.1 R33.1 | length 1.8
  Top Layer w0.254: R33.1@42.038,23.003 C21.1@43.879,23.003
NetC22_1: C22.1 R37.1 | length 1.9
  Top Layer w0.254: R37.1@42.038,5.207 43.853,5.207 C22.1@43.879,5.182
NetC25_1: C25.1 R45.1 | length 1.9
  Top Layer w0.254: C25.1@22.161,55.956 R45.1@24.078,55.956
NetC26_2: C26.2 C56.2 D6.2 Q3.4 R25.1 TP8.1 | length 15.1
  Top Layer w0.254: TP8.1@34.646,45.161 34.68,45.126 36.77,45.126 Q3.4@36.805,45.092 36.97,45.092 37.109,44.952 D6.2@37.109,43.082 D6.2@37.109,42.892 ; R25.1@35.496,42.628 36.845,42.628 D6.2@37.109,42.892 ; C56.2@43.879,40.723 43.879,40.698 42.874,39.694 40.666,39.694 39.711,40.649 39.711,40.699 39.031,40.699 37.212,42.518 37.212,42.789 D6.2@37.109,42.892
NetC27_2: C27.2 C68.2 D7.2 Q4.4 R26.1 TP10.1 | length 15.4
  Top Layer w0.254: TP10.1@34.646,25.908 34.678,25.876 36.772,25.876 Q4.4@36.805,25.843 36.99,25.843 37.129,25.703 37.129,23.477 D7.2@37.109,23.457 ; R26.1@35.496,23.13 36.972,23.13 37.109,23.267 D7.2@37.109,23.354 ; D7.2@37.212,23.267 37.212,22.697 38.964,20.946 C27.2@39.738,20.946 39.738,20.921 40.688,19.971 42.878,19.971 43.879,20.971 C68.2@43.879,20.996
NetC28_2: C28.2 C69.2 D8.2 Q5.4 R27.1 TP12.1 | length 15.3
  Top Layer w0.254: TP12.1@34.646,7.696 34.696,7.645 36.754,7.645 Q5.4@36.805,7.595 36.97,7.595 37.109,7.455 D8.2@37.109,5.483 ; R27.1@35.496,5.258 37.006,5.258 37.109,5.361 D8.2@37.109,5.483 ; C69.2@43.879,3.378 43.879,3.353 42.712,2.186 40.651,2.186 39.738,3.099 C28.2@39.738,3.124 38.837,3.124 37.212,4.748 37.212,5.38 D8.2@37.109,5.483
NetC42_1: C42.1 R46.1 | length 2
  Top Layer w0.254: C42.1@22.161,37.819 23.951,37.819 R46.1@24.078,37.946
NetC43_1: C43.1 R47.1 | length 1.9
  Top Layer w0.254: C43.1@22.161,19.998 R47.1@24.078,19.998
NetC46_2: C46.2 C75.2 D9.2 Q6.4 R40.1 TP20.1 | length 16.6
  Top Layer w0.254: C75.2@22.161,57.658 22.161,57.683 23.644,59.165 25.302,59.165 26.378,58.089 C46.2@26.378,58.064 26.378,58.039 26.726,57.691 27.627,57.691 28.802,56.516 28.802,55.947 D9.2@28.905,55.844 ; D9.2@28.905,55.654 D9.2@28.905,55.844 ; TP20.1@31.928,54.432 30.848,53.353 30.08,53.353 Q6.4@29.94,53.213 29.94,55.404 30.544,56.007 R40.1@30.544,56.032 29.093,56.032 D9.2@28.905,55.844
NetC47_2: C47.2 C76.2 D10.2 Q7.4 R41.1 TP22.1 | length 16.5
  Top Layer w0.254: C76.2@22.161,39.521 22.161,39.546 23.868,41.252 25.23,41.252 26.378,40.105 C47.2@26.378,40.08 ; C47.2@26.378,40.055 26.809,39.624 27.838,39.624 28.802,38.66 D10.2@28.802,37.7 ; D10.2@28.905,37.597 28.905,37.742 29.008,37.845 R41.1@30.544,37.845 30.544,37.82 29.94,37.216 Q7.4@29.94,35.344 31.458,35.344 TP22.1@32.131,36.017
NetC48_2: C48.2 C79.2 D11.2 Q8.4 R42.1 TP24.1 | length 16.1
  Top Layer w0.254: C79.2@22.161,21.7 22.161,21.725 23.462,23.025 25.425,23.025 26.378,22.072 C48.2@26.378,22.047 27.508,22.047 28.905,20.65 D11.2@28.905,19.81 ; D11.2@28.905,19.62 D11.2@28.905,19.81 ; Q8.4@29.94,17.475 Q8.4@30.404,17.475 ; TP24.1@32.156,18.186 31.445,17.475 Q8.4@30.404,17.475 ; D11.2@28.905,19.81 29.068,19.972 R42.1@30.544,19.972 30.544,17.615 Q8.4@30.404,17.475
NetC54_2: C54.2 D15.2 L2.4 P23.3 P23.4 R59.2 R60.2 | length 26.2
  Top Layer w0.508: R60.2@112.154,53.162 112.154,53.187 113.27,54.304 114.555,54.304 115.697,53.162 C54.2@115.697,53.137 115.753,53.193 118.445,53.193 ; D15.2@119.59,53.249 119.534,53.193 118.445,53.193 ; D15.2@119.836,53.003 120.235,52.603 125.136,52.603 P23.4@126.086,53.553 P23.3@128.626,53.553 ; L2.4@121.188,47.189 120.937,47.189 120.784,47.342 120.784,48.069 120.418,48.435 120.259,48.594 R59.2@118.409,48.594 118.44,48.626 118.44,53.188 118.445,53.193
NetC55_2: C55.2 R49.2 U2.8 | length 6.2
  Top Layer w0.508: R49.2@102.222,56.312 102.222,57.451 102.52,57.749 102.601,57.749 C55.2@102.922,58.07 ; C55.2@102.922,58.395 C55.2@102.922,58.07 ; U2.8@106.007,56.388 104.604,56.388 C55.2@102.922,58.07
NetC57_2: C57.2 R60.1 R63.1 | length 3.7
  Top Layer w0.508: C57.2@108.636,53.048 108.693,53.105 110.496,53.105 R60.1@110.554,53.162 R63.1@110.554,51.384
NetC59_1: C59.1 R68.1 R73.2 U4.1 | length 7.5
  Top Layer w0.254: U4.1@99.427,9.572 99.427,8.261 97.96,6.794 R73.2@97.935,6.794 98.283,6.446 98.385,6.446 99.637,5.194 C59.1@99.662,5.194 R68.1@101.389,5.194
NetC59_2: C59.2 R68.2 R71.1 U4.2 | length 6.4
  Top Layer w0.254: C59.2@99.662,6.794 R68.2@101.364,6.794 ; U4.2@100.697,9.572 100.697,7.462 R68.2@101.364,6.794 ; R71.1@103.057,6.794 R68.2@101.389,6.794 R68.2@101.364,6.794
NetC60_1: C60.1 R69.1 R72.2 U4.7 | length 6.7
  Top Layer w0.254: R72.2@99.935,18.021 R72.2@99.96,18.021 ; U4.7@100.697,15.117 100.697,17.284 R72.2@99.96,18.021 ; R69.1@103.389,18.021 C60.1@101.662,18.021 R72.2@99.96,18.021
NetC60_2: C60.2 R69.2 R70.1 U4.6 | length 9.2
  Top Layer w0.254: C60.2@101.662,19.621 R69.2@103.389,19.621 103.737,19.273 103.78,19.273 R70.1@105.032,18.021 ; U4.6@101.967,15.117 101.967,16.623 102.489,17.145 104.181,17.145 104.684,17.648 104.684,17.673 R70.1@105.032,18.021 ; R70.1@105.057,18.021 R70.1@105.032,18.021
NetC62_2: C62.2 D15.1 L2.3 P23.1 P23.2 R63.2 R67.2 | length 31.3
  Top Layer w0.508: R63.2@112.154,51.384 112.154,51.359 113.119,50.394 114.656,50.394 115.697,51.435 C62.2@115.697,51.46 ; C62.2@115.918,51.228 115.918,51.243 117.54,51.243 v1(117.577,51.206) ; v1(119.465,52.161) 119.502,52.124 119.502,51.437 D15.1@119.59,51.349 119.59,49.965 119.888,49.668 121.517,49.668 122.864,48.32 122.864,45.039 122.472,44.647 L2.3@121.23,44.647 120.98,44.647 119.785,43.453 119.533,43.453 119.492,43.412 R67.2@119.492,43.387 ; D15.1@119.836,51.595 120.134,51.892 124.938,51.892 125.817,51.013 P23.1@128.626,51.013
  Bottom Layer w0.508: v1(117.577,51.206) 118.494,52.124 119.428,52.124 v1(119.465,52.161) v1@119.434,52.191
NetC65_2: C65.2 R74.1 R76.2 U4.5 | length 10.6
  Top Layer w0.254: U4.5@103.237,15.117 103.237,16.42 103.508,16.691 105.37,16.691 106.7,18.021 R74.1@106.725,18.021 106.705,18.002 R76.2@106.705,14.897 C65.2@108.687,14.897
NetC66_2: C66.2 R75.1 R77.2 U4.3 | length 9.9
  Top Layer w0.254: U4.3@101.967,9.572 101.967,8.843 102.849,7.961 103.534,7.961 104.7,6.794 R75.1@104.725,6.794 104.725,7.582 106.68,9.538 R77.2@106.705,9.538 C66.2@108.687,9.538
NetC67_1: C67.1 R80.1 R90.2 U5.1 | length 7.5
  Top Layer w0.254: R90.2@87.208,6.794 R90.2@87.233,6.794 ; U5.1@88.173,9.572 88.173,7.735 R90.2@87.233,6.794 ; R80.1@90.84,5.194 C67.1@89.057,5.194 88.709,5.542 88.485,5.542 R90.2@87.233,6.794
NetC67_2: C67.2 R80.2 R89.1 U5.2 | length 6.4
  Top Layer w0.254: U5.2@89.443,9.572 89.443,8.753 89.057,8.367 C67.2@89.057,6.794 R80.2@90.84,6.794 R89.1@92.491,6.794
NetC77_2: C77.2 R4.1 R83.1 R111.2 | length 8.5
  Top Layer w0.508: R111.2@72.069,18.504 72.082,18.517 74.943,18.517 C77.2@74.955,18.529 76.719,18.529 R83.1@76.884,18.364 76.847,18.327 76.847,16.281 76.549,15.983 R4.1@75.422,15.983
NetC80_2: C80.2 Q10.1 R91.1 R94.2 | length 5
  Top Layer w0.254: Q10.1@76.611,10.651 78.127,10.651 C80.2@78.313,10.837 R94.2@79.939,10.837 R91.1@81.513,10.837
NetC82_2: C82.2 R92.1 R95.2 U5.3 | length 10.5
  Top Layer w0.254: U5.3@90.713,9.572 90.713,8.296 91.237,7.772 93.13,7.772 94.108,6.794 R92.1@94.133,6.794 94.133,8.792 94.879,9.538 R95.2@94.904,9.538 C82.2@96.987,9.538
NetD2_2: D2.2 R7.2 | length 1.9
  Top Layer w0.254: R7.2@68.745,75.641 68.745,76.683 69.24,77.178 D2.2@69.24,77.368
NetD6_1: D6.1 R22.1 | length 1.8
  Top Layer w0.254: R22.1@35.496,41.028 37.006,41.028 37.109,40.925 D6.1@37.109,40.802
NetD7_1: D7.1 R23.1 | length 1.9
  Top Layer w0.254: R23.1@35.496,21.504 36.972,21.504 37.109,21.367 D7.1@37.109,21.177
NetD8_1: D8.1 R24.1 | length 1.9
  Top Layer w0.254: R24.1@35.496,3.658 36.845,3.658 37.109,3.393 D8.1@37.109,3.203
NetD9_1: D9.1 R34.1 | length 1.9
  Top Layer w0.254: D9.1@28.905,57.934 28.905,57.761 29.008,57.658 R34.1@30.544,57.658
NetD10_1: D10.1 R35.1 | length 1.9
  Top Layer w0.254: D10.1@28.905,39.877 28.905,39.687 29.096,39.496 R35.1@30.544,39.496
NetD11_1: D11.1 R36.1 | length 1.8
  Top Layer w0.254: D11.1@28.905,21.9 28.905,21.777 29.008,21.674 R36.1@30.544,21.674
NetD13_1: D13.1 R112.2 | length 14.4
  Top Layer w0.254: R112.2@86.72,78.539 86.745,78.539 87.093,78.191 87.093,77.637 v1(87.4,77.329) ; v1(94.048,70.757) 94.996,69.809 D13.1@96.009,69.809
  L3 w0.254: v1(87.4,77.329) 89.504,77.329 91.706,75.126 91.706,73.099 v1(94.048,70.757)
NetD14_1: D14.1 R104.2 | length 11.3
  Top Layer w0.254: R104.2@89.499,78.463 89.524,78.463 89.872,78.115 89.872,78.09 90.73,77.232 90.73,73.836 92.662,71.905 D14.1@96.041,71.905
NetD16_1: D16.1 R4.2 R83.2 | length 7.2
  Top Layer w0.508: D16.1@77.445,20.499 77.445,20.357 78.893,18.909 79.563,18.909 79.884,18.588 R83.2@79.884,18.364 79.884,16.375 79.492,15.983 R4.2@78.422,15.983
NetD17_1: D17.1 R105.2 | length 2.1
  Top Layer w0.254: D17.1@84.261,14.287 84.287,14.313 R105.2@84.287,16.332
NetD19_2: D19.2 R121.2 | length 2.4
  Top Layer w0.254: D19.2@91.905,76.022 91.905,76.866 92.203,77.165 92.203,78.249 R121.2@92.263,78.309
NetJP2_1: JP2.1 P10.2 R115.2 | length 11.1
  Top Layer w0.254: P10.2@76.974,77.136 78.122,78.283 79.027,78.283 JP2.1@80.452,79.708 81.677,78.482 81.677,75.468 82.349,74.796 R115.2@82.349,73.903
NetJP2_2: JP2.2 Q11.3 R114.2 | length 22.5
  Top Layer w0.254: R114.2@78.136,70.523 R114.2@78.137,70.524 79.475,70.524 v1(80.261,71.31) ; JP2.2@80.452,77.168 80.346,77.063 80.346,71.396 v1(80.261,71.31) ; Q11.3@92.885,69.247 92.885,70.328 91.903,71.31 v1(80.261,71.31)
NetP2_1: P2.1 R61.1 | length 6.8
  Top Layer w0.254: R61.1@119.312,34.954 126.056,34.954 P2.1@126.086,34.925
NetP2_3: P2.3 R78.1 | length 22.6
  Top Layer w0.254: R78.1@105.634,37.424 105.634,37.399 105.982,37.051 107.288,37.051 111.124,33.215 121.023,33.215 121.853,32.385 P2.3@126.086,32.385
NetP2_5: P2.5 R87.1 | length 22.5
  Top Layer w0.254: R87.1@105.081,33.496 108.532,33.496 112.183,29.845 P2.5@126.086,29.845
NetP2_7: P2.7 R102.1 | length 22.9
  Top Layer w0.254: R102.1@105.067,31.797 105.922,31.797 109.271,28.448 115.807,28.448 116.467,27.788 119.863,27.788 120.345,27.305 P2.7@126.086,27.305
NetP2_9: P2.9 R8.1 | length 32.5
  Top Layer w0.254: R8.1@98.229,29.064 99.248,29.064 99.611,28.702 107.521,28.702 108.865,27.358 108.865,25.225 111.281,22.809 124.13,22.809 P2.9@126.086,24.765
NetP2_11: P2.11 R10.1 | length 30.8
  Top Layer w0.254: R10.1@98.239,27.433 107.336,27.433 108.359,26.41 108.359,25.085 111.15,22.293 126.017,22.293 P2.11@126.086,22.225
NetP2_13: P2.13 R28.1 | length 25.5
  Top Layer w0.254: R28.1@106.108,26.352 107.203,26.352 107.573,25.983 107.573,24.959 108.814,23.718 108.814,21.023 109.339,20.498 113.946,20.498 115.504,18.94 120.143,18.94 120.888,19.685 P2.13@126.086,19.685
NetP2_15: P2.15 R29.1 | length 25.3
  Top Layer w0.254: R29.1@106.121,24.536 107.349,24.536 108.357,23.528 108.357,19.583 109.908,18.032 119.823,18.032 120.71,17.145 P2.15@126.086,17.145
NetP2_17: P2.17 R30.1 | length 26.2
  Top Layer w0.254: R30.1@106.172,22.962 v1(107.427,22.962)
  Bottom Layer w0.254: v1(107.427,22.962) 108.671,22.962 108.975,23.265 116.221,23.265 118.731,20.756 118.731,16.416 120.542,14.605 P2.17@126.086,14.605
NetP5_5: P5.5 R13.1 | length 13.6
  Top Layer w0.254: R13.1@112.458,74.32 112.468,74.33 P5.5@126.086,74.33
NetP5_7: P5.7 R14.1 | length 14.5
  Top Layer w0.254: R14.1@112.458,71.628 112.458,71.653 112.806,72.001 112.831,72.001 113.627,72.796 120.421,72.796 121.428,71.79 P5.7@126.086,71.79
NetP5_8: P5.8 R15.2 | length 10.2
  Top Layer w0.254: R15.2@119.329,71.628 119.329,71.603 120.269,70.663 123.41,70.663 123.414,70.659 126.554,70.659 127.495,71.599 128.435,71.599 P5.8@128.626,71.79
NetP5_9: P5.9 R16.1 | length 14.5
  Top Layer w0.254: R16.1@112.458,69.147 112.458,69.172 112.806,69.52 112.831,69.52 113.517,70.206 123.19,70.206 124.146,69.25 P5.9@126.086,69.25
NetP5_10: P5.10 R17.2 | length 10.3
  Top Layer w0.254: R17.2@119.316,69.266 122.483,69.266 123.63,68.119 127.495,68.119 P5.10@128.626,69.25
NetP5_11: P5.11 R18.1 | length 14.5
  Top Layer w0.254: R18.1@112.458,66.692 113.058,67.291 113.292,67.291 113.783,67.782 120.747,67.782 121.819,66.71 P5.11@126.086,66.71
NetP5_12: P5.12 R19.2 | length 10.2
  Top Layer w0.254: R19.2@119.329,66.667 119.329,66.642 120.392,65.579 127.495,65.579 P5.12@128.626,66.71
NetP5_13: P5.13 R20.1 | length 6.8
  Top Layer w0.254: R20.1@119.329,64.186 119.345,64.17 P5.13@126.086,64.17
NetP9_1: P9.1 R64.1 | length 15.1
  Top Layer w0.254: R64.1@100.448,76.575 101.95,76.575 102.562,77.187 v1(102.562,79.328)
  L3 w0.254: P9.1@100.149,88.144 101.45,88.144 102.562,87.033 v1(102.562,79.328)
NetP9_3: P9.3 R125.1 | length 13.3
  Top Layer w0.254: R125.1@97.563,76.619 v1(98.814,76.619)
  L3 w0.254: P9.3@97.609,88.144 98.864,86.89 98.864,76.668 v1(98.814,76.619)
NetP9_5: P9.5 R126.1 | length 13.5
  Top Layer w0.254: R126.1@94.856,76.494 v1(96.196,76.494)
  L3 w0.254: P9.5@95.069,88.144 96.246,86.968 96.246,76.544 v1(96.196,76.494)
NetP9_7: P9.7 R103.1 | length 39.4
  Top Layer w0.254: R103.1@95.76,51.344 R103.1@95.76,51.369 96.108,51.717 96.108,54.906 96.444,55.242 96.444,56.574 96.363,56.574 v1(96.06,56.877)
  L3 w0.254: P9.7@92.529,88.144 93.807,86.866 93.807,73.666 96.852,70.621 96.852,57.986 96.146,57.279 96.146,56.962 v1(96.06,56.877)
NetP9_8: P9.8 R121.1 | length 6
  Top Layer w0.254: R121.1@92.263,79.909 92.529,80.175 92.529,85.604 P9.8@92.398,85.473
NetP9_9: P9.9 R3.1 | length 12.6
  Top Layer w0.254: R3.1@88.857,76.833 88.832,76.833 88.832,77.573 87.901,78.504 87.901,83.615 88.684,84.398 88.684,86.839 P9.9@89.989,88.144
NetP9_10: P9.10 R104.1 | length 5.9
  Top Layer w0.254: R104.1@89.499,80.063 89.499,81.521 89.989,82.011 89.989,85.604 P9.10@89.858,85.473
NetP9_11: P9.11 R2.1 | length 12.4
  Top Layer w0.254: R2.1@86.133,76.688 86.133,77.547 85.667,78.014 85.667,82.019 86.04,82.393 86.04,86.735 P9.11@87.449,88.144
NetP9_12: P9.12 R112.1 | length 6
  Top Layer w0.254: R112.1@86.72,80.139 86.72,84.734 87.449,85.464 87.449,85.604 P9.12@87.318,85.473
NetP9_13: P9.13 R6.1 | length 8.8
  Top Layer w0.254: R6.1@83.861,80.112 83.861,81.268 83.432,81.696 83.432,86.668 P9.13@84.909,88.144
NetP10_1: P10.1 R113.1 | length 2.9
  Top Layer w0.254: P10.1@76.974,74.596 78.144,73.426 R113.1@78.144,72.199
NetQ1_4: Q1.4 Q2.3 R5.2 TP2.1 | length 21.6
  Top Layer w0.254: v1(55.474,76.073) 56.413,76.073 Q1.4@56.439,76.048 ; R5.2@67.031,78.956 66.929,79.057 TP2.1@66.929,80.569 66.992,80.569 68.186,81.763 v1(68.25,81.763) 69.015,82.527 69.015,82.901 Q2.3@69.273,83.16
  L3 w0.254: v1(55.474,76.073) 61.392,81.991 67.901,81.991 68.129,81.763 v1(68.25,81.763)
NetQ9_2: Q9.2 R97.2 R99.2 | length 3.6
  Top Layer w0.254: Q9.2@84.232,63.5 84.937,63.5 85.392,63.955 85.392,63.98 85.74,64.328 R99.2@85.765,64.328 85.902,64.464 R97.2@85.902,66.001
NetQ9_3: Q9.3 R88.2 | length 2.1
  Top Layer w0.254: R88.2@84.01,66.116 83.987,66.093 83.987,65.111 84.232,64.866 Q9.3@84.232,64.15
NetQ9_5: Q9.5 R93.2 R100.1 | length 6.1
  Top Layer w0.254: R100.1@80.579,66.187 80.781,65.984 R93.2@80.781,64.328 81.129,64.676 81.216,64.676 81.303,64.763 82.952,64.763 83.101,64.614 83.101,63.836 82.848,63.583 82.475,63.583 Q9.5@82.392,63.5
NetQ9_6: Q9.6 R100.2 | length 7.4
  Top Layer w0.254: R100.2@80.781,67.741 80.806,67.741 81.586,66.962 81.586,65.429 81.796,65.219 83.146,65.219 83.566,64.799 83.566,64.507 83.555,64.495 83.555,63.64 82.878,62.963 82.8,62.963 Q9.6@82.652,62.814 ; Q9.6@82.392,62.85 Q9.6@82.453,62.911
NetQ10_3: Q10.3 R84.2 | length 2.6
  Top Layer w0.254: R84.2@72.044,12.475 72.069,12.475 72.943,11.601 Q10.3@74.311,11.601
NetQ11_1: Q11.1 R116.2 | length 2
  Top Layer w0.254: Q11.1@91.935,66.947 91.935,65.459 92.247,65.147 R116.2@92.272,65.147
NetR9_1: R9.1 SW1.1 SW1.2 | length 9.9
  Top Layer w0.254: R9.1@109.245,79.929 R9.1@109.22,79.929 109.22,80.745 109.445,80.97 111.659,80.97 SW1.1@111.685,80.944 SW1.2@118.185,80.944
NetR21_2: R21.2 R66.1 | length 35.7
  Top Layer w0.508: R66.1@78.93,23.927 78.93,23.952 79.961,24.982 80.507,24.982 v1(80.543,25.019) ; v1(107.594,37.77) R21.2@108.801,37.77
  Bottom Layer w0.508: v1(80.543,25.019) 80.58,25.056 80.739,25.056 84.366,28.683 84.366,28.892 91.948,36.474 106.299,36.474 v1(107.594,37.77)
NetR50_1: R50.1 R56.2 | length 2.6
  Top Layer w0.254: R56.2@116.243,58.471 116.243,58.496 116.591,58.844 116.871,58.844 118.11,60.084 R50.1@118.135,60.084
NetR62_1: R62.1 U3.1 | length 3.7
  Top Layer w0.254: R62.1@101.87,45.163 U3.1@105.356,45.163
  Top Layer w0.508: R62.1@101.737,45.296 R62.1@101.87,45.163 ; U3.1@105.356,45.163 U3.1@105.371,45.147
NetR65_1: R65.1 U3.4 | length 3.6
  Top Layer w0.254: R65.1@101.737,41.336 R65.1@101.737,41.336 U3.4@105.371,41.337
NetR79_2: R79.2 R86.2 U3.8 | length 8.6
  Top Layer w0.254: R79.2@107.494,47.201 107.494,47.176 109.513,45.158 110.906,45.158 U3.8@110.916,45.147 110.916,46.256 113.149,48.489 R86.2@113.149,48.514
NetR81_2: R81.2 U2.7 | length 5.7
  Top Layer w0.254: R81.2@102.222,60.579 103.208,60.579 104.267,59.52 104.267,58.318 104.927,57.658 U2.7@106.007,57.658
NetR82_2: R82.2 R85.1 U5.5 | length 4.8
  Top Layer w0.254: R85.1@90.84,18.021 R82.2@92.491,18.021 92.491,16.353 91.983,15.845 U5.5@91.983,15.117
NetR105_1: R105.1 R106.1 | length 1.7
  Top Layer w0.254: R105.1@84.287,17.932 R106.1@84.287,19.66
